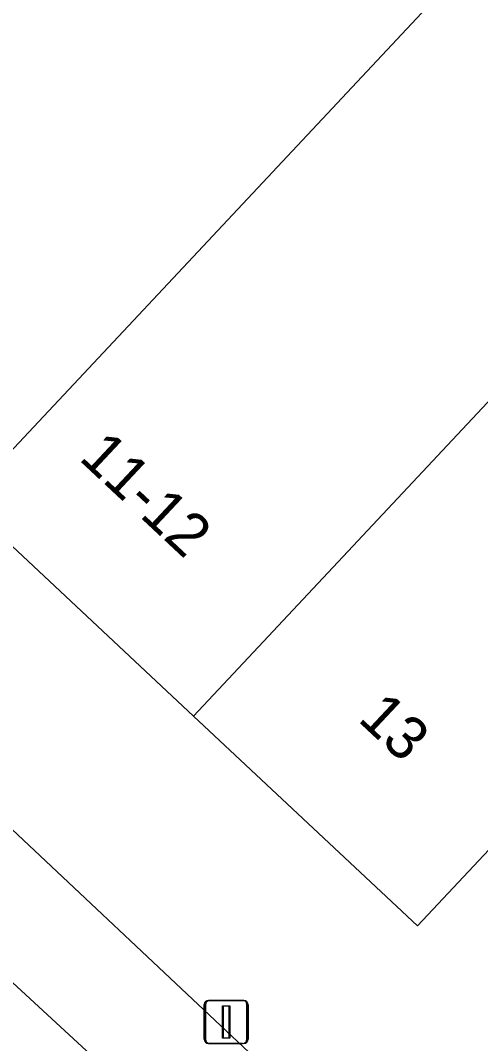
# Model space of a CAD drawing. Extents: x 159039 to 160102, y 381214 to 382524.
# Drawn here: x 159519.96 to 159530.64, y 381598.42 to 381622.17 of the extents above; entities that cross this region are included whole.
import ezdxf

# ---------------------------------------------------------------- set-up
doc = ezdxf.new("R2010")
doc.units = 0
for name, color, linetype in [('IMGEO_Groenvoorziening', 7, 'Continuous'), ('IMGEO_Lichtmast', 7, 'Continuous'), ('IMGEO_Pand', 7, 'Continuous'), ('IMGEO_Pand_nummerreeks', 7, 'Continuous'), ('IMGEO_Voetpad_open', 7, 'Continuous')]:
    doc.layers.add(name, color=color, linetype=linetype)

msp = doc.modelspace()

# ---------------------------------------------------------------- linework, layer by layer
at = {"layer": 'IMGEO_Groenvoorziening'}
msp.add_lwpolyline([(159518.444, 381604.625), (159516.67, 381602.701), (159524.096, 381595.85), (159525.918, 381597.602)], close=True, dxfattribs=at)
msp.add_lwpolyline([(159527.059, 381593.822), (159530.122, 381593.652), (159525.918, 381597.602), (159524.096, 381595.85), (159516.67, 381602.701)], dxfattribs=at)
at = {"layer": 'IMGEO_Lichtmast'}
for p, q in [((159524.228, 381598.523), (159524.228, 381599.323)), ((159524.228, 381599.323), (159524.228, 381598.523)), ((159524.254, 381598.52), (159524.254, 381599.32)), ((159524.254, 381599.32), (159524.254, 381598.52)), ((159524.328, 381599.423), (159525.118, 381599.423)), ((159525.118, 381599.423), (159524.328, 381599.423)), ((159524.354, 381599.42), (159525.144, 381599.42)), ((159525.144, 381599.42), (159524.354, 381599.42)), ((159525.218, 381599.323), (159525.218, 381598.523)), ((159525.218, 381598.523), (159525.218, 381599.323)), ((159525.244, 381599.32), (159525.244, 381598.52)), ((159525.244, 381598.52), (159525.244, 381599.32)), ((159525.118, 381598.423), (159524.328, 381598.423)), ((159524.328, 381598.423), (159525.118, 381598.423))]:
    msp.add_line(p, q, dxfattribs=at)
for points in [[(159524.648, 381599.298), (159524.798, 381599.298), (159524.798, 381598.548), (159524.648, 381598.548), (159524.648, 381599.298)], [(159524.674, 381599.295), (159524.824, 381599.295), (159524.824, 381598.545), (159524.674, 381598.545), (159524.674, 381599.295)]]:
    msp.add_lwpolyline(points, dxfattribs=at)
for centre, start, end in [((159524.328, 381599.323), 90, 180), ((159524.328, 381599.323), 90, 180), ((159524.354, 381599.32), 90, 180), ((159524.354, 381599.32), 90, 180), ((159525.118, 381599.323), 0, 90), ((159525.118, 381599.323), 360, 90), ((159525.144, 381599.32), 0, 90), ((159525.144, 381599.32), 360, 90), ((159524.328, 381598.523), 180, 270), ((159524.328, 381598.523), 180, 270), ((159524.354, 381598.52), 180, 270), ((159524.354, 381598.52), 180, 270), ((159525.118, 381598.523), 270, 0), ((159525.118, 381598.523), 270, 0), ((159525.144, 381598.52), 270, 0), ((159525.144, 381598.52), 270, 0)]:
    msp.add_arc(centre, 0.1, start, end, dxfattribs=at)
at = {"layer": 'IMGEO_Pand'}
for points in [[(159518.65, 381611.007), (159531.579, 381624.81), (159526.253, 381629.802), (159513.321, 381615.996)], [(159537.15, 381620.079), (159536.341, 381620.801), (159536.144, 381620.977), (159535.924, 381620.737), (159531.579, 381624.81), (159518.65, 381611.007), (159523.98, 381606.018)], [(159537.15, 381620.079), (159523.98, 381606.018), (159529.176, 381601.153), (159542.198, 381615.033), (159542.475, 381615.328)]]:
    msp.add_lwpolyline(points, close=True, dxfattribs=at)
at = {"layer": 'IMGEO_Voetpad_open'}
for points in [[(159541.295, 381603.687), (159543.998, 381606.571), (159544.427, 381607.028), (159546.113, 381605.448), (159548.119, 381607.324), (159546.355, 381608.976), (159547.363, 381610.113), (159544.08, 381613.241), (159546.996, 381616.431), (159545.216, 381618.097), (159542.475, 381615.328), (159542.198, 381615.033), (159529.176, 381601.153), (159523.98, 381606.018), (159518.65, 381611.007), (159513.321, 381615.996), (159507.992, 381620.984), (159502.663, 381625.973), (159500, 381628.466), (159497.333, 381630.962), (159491.8, 381635.765)], [(159516.971, 381602.179), (159516.644, 381602.673), (159516.67, 381602.701), (159518.444, 381604.625), (159525.918, 381597.602), (159530.122, 381593.652)]]:
    msp.add_lwpolyline(points, dxfattribs=at)

# ---------------------------------------------------------------- texts
at = {"layer": 'IMGEO_Pand_nummerreeks'}
for s, p in [('11-12', (159521.295, 381611.983)), ('13', (159527.765, 381605.925))]:
    msp.add_text(s, height=1, rotation=316.8889, dxfattribs=at).set_placement(p)

doc.saveas('drawing.dxf')
